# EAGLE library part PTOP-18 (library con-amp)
AMP connector
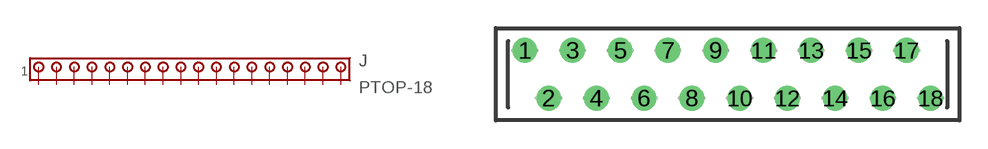
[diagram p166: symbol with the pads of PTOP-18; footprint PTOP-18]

Designator prefix J

## PTOP-18 (OC_FARNELL: unknown; OC_NEWARK: unknown)  [PTOP-18]
1  1  pas
2  2  pas
3  3  pas
4  4  pas
5  5  pas
6  6  pas
7  7  pas
8  8  pas
9  9  pas
10  10  pas
11  11  pas
12  12  pas
13  13  pas
14  14  pas
15  15  pas
16  16  pas
17  17  pas
18  18  pas

## Footprint PTOP-18 (pad centres in mm)
AMP connector
drill 0.813 round: 1 -10.795,1.27; 2 -9.525,-1.27; 3 -8.255,1.27; 4 -6.985,-1.27; 5 -5.715,1.27; 6 -4.445,-1.27; 7 -3.175,1.27; 8 -1.905,-1.27; 9 -0.635,1.27; 10 0.635,-1.27; 11 1.905,1.27; 12 3.175,-1.27; 13 4.445,1.27; 14 5.715,-1.27; 15 6.985,1.27; 16 8.255,-1.27; 17 9.525,1.27; 18 10.795,-1.27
